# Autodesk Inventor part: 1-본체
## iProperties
Created: 2015-01
Part Number: 1-본체
Document SubType Name: Modeling
Designer: Administrator
Density: 2.71 g/cm^3
Material: 알루미늄-6061
Mass: 1021.81 g
Surface Area: 1062.77 cm^2
Volume: 377.053 cm^3
Author: Administrator
